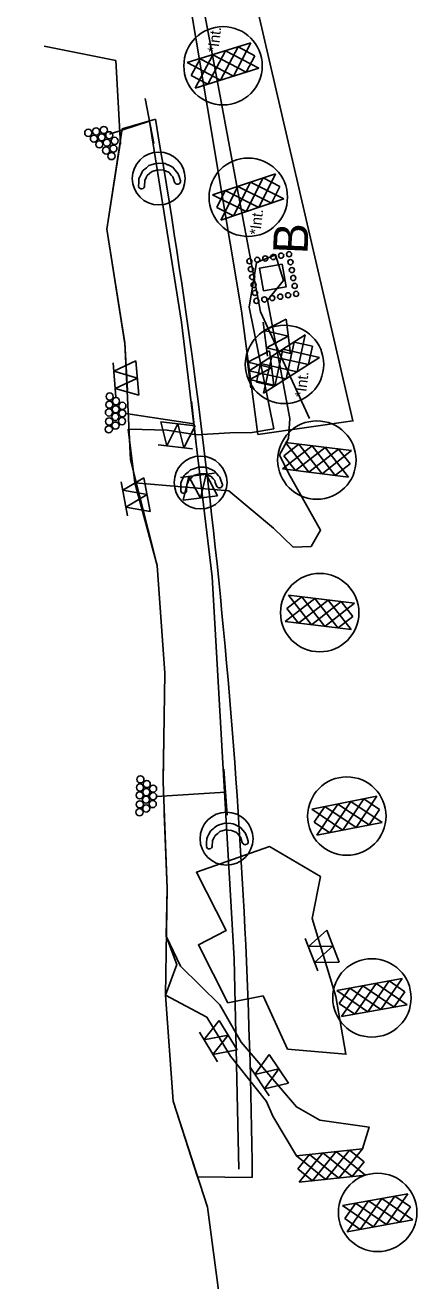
# Model space of a CAD drawing. Extents: x 400935 to 481562, y 415700 to 505362.
# Drawn here: x 481232 to 481402, y 491347 to 491893 of the extents above; entities that cross this region are included whole.
import ezdxf

# ---------------------------------------------------------------- set-up
doc = ezdxf.new("R2010")
doc.units = 0
for name, color, linetype in [('Coir Fiber Wattle with PAM Final CELL', 7, 'Continuous'), ('Drain Terminator Final CELL', 7, 'Continuous'), ('Earth Berm for Slope Drains Final', 7, 'Continuous'), ('Label B Final CELL', 7, 'Continuous'), ('Matting on Slope Note Final CELL', 7, 'Continuous'), ('Old_Level_2', 7, 'Continuous'), ('Rock Inlet Sediment Trap Type B Final CELL', 7, 'Continuous'), ('Rock Silt Check Type A CG CELL', 7, 'Continuous'), ('Rock Silt Check Type A with Matting and PAM Final CELL', 7, 'Continuous'), ('Scratch_Level_3', 7, 'Continuous'), ('Scratch_Level_4', 7, 'Continuous'), ('Slope Drain Final', 7, 'Continuous'), ('Slope Drain Inlet Final CELL', 7, 'Continuous'), ('Special Sediment Control Fence Section Both CELL', 7, 'Continuous'), ('Special Sediment Control Fence Section CG CELL', 7, 'Continuous'), ('Temporary Silt Fence Both', 7, 'Continuous'), ('Temporary Silt Fence CG', 7, 'Continuous'), ('Temporary Silt Fence Final', 7, 'Continuous')]:
    doc.layers.add(name, color=color, linetype=linetype)

msp = doc.modelspace()

# ---------------------------------------------------------------- linework, layer by layer
at = {"layer": 'Coir Fiber Wattle with PAM Final CELL'}
for p, q in [((481289.38, 491830.27), (481286.95, 491829.54)), ((481289.38, 491830.27), (481289.39, 491830.28)), ((481292.02, 491830.14), (481289.39, 491830.28)), ((481283.79, 491825.27), (481283.67, 491823.42)), ((481283.79, 491825.27), (481283.81, 491825.61)), ((481284.45, 491826.94), (481283.81, 491825.61)), ((481284.89, 491827.87), (481284.45, 491826.94)), ((481286.01, 491828.78), (481284.89, 491827.87)), ((481286.95, 491829.54), (481286.01, 491828.78)), ((481292.02, 491830.14), (481293.1, 491829.65)), ((481294.11, 491829.18), (481293.1, 491829.65)), ((481294.11, 491829.18), (481294.33, 491829.09)), ((481295.27, 491827.99), (481294.33, 491829.09)), ((481295.99, 491827.15), (481295.27, 491827.99)), ((481296.23, 491826.39), (481295.99, 491827.15)), ((481296.69, 491824.91), (481296.23, 491826.39)), ((481302.65, 491694.66), (481302.04, 491693.31)), ((481303.07, 491695.6), (481302.65, 491694.66)), ((481304.17, 491696.54), (481303.07, 491695.6)), ((481305.09, 491697.32), (481304.17, 491696.54)), ((481307.5, 491698.12), (481305.09, 491697.32)), ((481307.5, 491698.12), (481307.51, 491698.12)), ((481310.14, 491698.05), (481307.51, 491698.12)), ((481310.14, 491698.05), (481311.23, 491697.58)), ((481312.26, 491697.14), (481311.23, 491697.58)), ((481312.26, 491697.14), (481312.47, 491697.05)), ((481313.44, 491695.97), (481312.47, 491697.05)), ((481314.18, 491695.15), (481313.44, 491695.97)), ((481314.44, 491694.4), (481314.18, 491695.15)), ((481314.94, 491692.93), (481314.44, 491694.4)), ((481302.03, 491692.98), (481301.96, 491691.12)), ((481302.03, 491692.98), (481302.04, 491693.31)), ((481314.38, 491540.92), (481313.93, 491540)), ((481315.51, 491541.82), (481314.38, 491540.92)), ((481316.45, 491542.57), (481315.51, 491541.82)), ((481318.89, 491543.29), (481316.45, 491542.57)), ((481318.89, 491543.29), (481318.9, 491543.29)), ((481321.53, 491543.13), (481318.9, 491543.29)), ((481321.53, 491543.13), (481322.61, 491542.63)), ((481323.61, 491542.15), (481322.61, 491542.63)), ((481323.61, 491542.15), (481323.82, 491542.05)), ((481324.76, 491540.94), (481323.82, 491542.05)), ((481325.47, 491540.1), (481324.76, 491540.94)), ((481313.25, 491538.34), (481313.12, 491536.48)), ((481313.25, 491538.34), (481313.28, 491538.67)), ((481313.93, 491540), (481313.28, 491538.67)), ((481325.7, 491539.34), (481325.47, 491540.1)), ((481326.15, 491537.86), (481325.7, 491539.34))]:
    msp.add_line(p, q, dxfattribs=at)
for points in [[(481281.1, 491823.09), (481281.17, 491824.65), (481281.26, 491826.46), (481281.61, 491827.22), (481282.05, 491828.13), (481282.82, 491829.75), (481282.85, 491829.78), (481283.18, 491830.07), (481283.24, 491830.12), (481283.97, 491830.73), (481284.48, 491831.17), (481285.59, 491832.11), (481286.58, 491832.44), (481289.01, 491833.22), (481289.02, 491833.22), (481291.65, 491833.06), (481292.68, 491832.99), (481293.69, 491832.49), (481293.91, 491832.39), (481294.77, 491831.96), (481295.42, 491831.64), (481295.58, 491831.56), (481295.91, 491831.4), (481295.91, 491831.39), (481296.88, 491830.24), (481297.75, 491829.21), (481298.27, 491828.59), (481298.82, 491826.92), (481299.3, 491825.45)], [(481299.39, 491690.73), (481299.43, 491692.29), (481299.47, 491694.11), (481299.81, 491694.87), (481300.22, 491695.8), (481300.95, 491697.44), (481300.98, 491697.46), (481301.31, 491697.76), (481301.36, 491697.81), (481302.08, 491698.45), (481302.57, 491698.89), (481303.67, 491699.86), (481304.65, 491700.21), (481307.06, 491701.05), (481307.07, 491701.06), (481309.7, 491700.95), (481310.73, 491700.91), (481311.76, 491700.44), (481311.97, 491700.34), (481312.84, 491699.93), (481313.51, 491699.62), (481313.66, 491699.55), (481313.99, 491699.4), (481314, 491699.39), (481315, 491698.26), (481315.89, 491697.25), (481316.42, 491696.64), (481317.01, 491694.99), (481317.53, 491693.53)], [(481310.54, 491536.18), (481310.63, 491537.73), (481310.73, 491539.55), (481311.1, 491540.3), (481311.54, 491541.21), (481312.32, 491542.82), (481312.35, 491542.85), (481312.69, 491543.13), (481312.75, 491543.18), (481313.48, 491543.8), (481313.99, 491544.22), (481315.12, 491545.16), (481316.11, 491545.47), (481318.54, 491546.24), (481318.56, 491546.24), (481321.19, 491546.05), (481322.21, 491545.98), (481323.22, 491545.47), (481323.44, 491545.36), (481324.29, 491544.92), (481324.94, 491544.6), (481325.1, 491544.52), (481325.43, 491544.35), (481325.43, 491544.35), (481326.39, 491543.18), (481327.25, 491542.14), (481327.76, 491541.52), (481328.29, 491539.85), (481328.76, 491538.37)]]:
    msp.add_lwpolyline(points, dxfattribs=at)
for centre in [(481289.85, 491826.5), (481308.05, 491694.36), (481319.32, 491539.51)]:
    msp.add_circle(centre, 11.5, dxfattribs=at)
for centre, radius, start, end in [((481297.98, 491825.28), 1.33, 196.1041, 7.2167), ((481282.39, 491823.25), 1.3, 187.2167, 7.2167), ((481300.67, 491690.93), 1.3, 188.5949, 8.5949), ((481316.21, 491693.33), 1.33, 197.4823, 8.5949), ((481311.83, 491536.33), 1.3, 186.6946, 6.6946), ((481327.44, 491538.21), 1.33, 195.5819, 6.6946)]:
    msp.add_arc(centre, radius, start, end, dxfattribs=at)
at = {"layer": 'Drain Terminator Final CELL'}
for centre in [(481259.24, 491846.34), (481262.62, 491846.95), (481265.99, 491847.55), (481268.35, 491845.3), (481261.69, 491843.79), (481264.05, 491841.34), (481265.07, 491844.4), (481267.33, 491842.05), (481270.71, 491842.85), (481266.97, 491838.69), (481269.33, 491836.25), (481270.16, 491839.5), (481268.54, 491731.72), (481268.38, 491728.19), (481271.14, 491726.16), (481271.3, 491729.69), (481274.06, 491727.66), (481268.22, 491724.8), (481268.31, 491720.85), (481270.99, 491722.9), (481273.9, 491721), (481274.05, 491724.4), (481268.16, 491717.46), (481271.09, 491719.09), (481281.72, 491561.75), (481281.88, 491565.28), (481284.64, 491563.25), (481287.4, 491561.22), (481281.56, 491558.36), (481284.33, 491556.46), (481284.48, 491559.72), (481287.39, 491557.96), (481281.5, 491551.02), (481281.65, 491554.41), (481284.43, 491552.65), (481287.24, 491554.56)]:
    msp.add_circle(centre, 1.55, dxfattribs=at)
at = {"layer": 'Earth Berm for Slope Drains Final'}
msp.add_lwpolyline([(481324.6, 491395.83), (481322.67, 491487.21), (481317.74, 491572.32), (481313.05, 491653.33), (481299.73, 491764.1), (481285.85, 491851.48)], dxfattribs=at)
at = {"layer": 'Matting on Slope Note Final CELL'}
for p, q in [((481288.4, 491852.22), (481274.02, 491848.1)), ((481274.02, 491848.1), (481267.26, 491804.49)), ((481267.26, 491804.49), (481275.12, 491755)), ((481275.12, 491755), (481277.63, 491704.26)), ((481277.63, 491704.26), (481289.1, 491658.31)), ((481289.1, 491658.31), (481292.54, 491611.44)), ((481292.54, 491611.44), (481291.71, 491564.28)), ((481291.71, 491564.28), (481293.47, 491517.85)), ((481293.47, 491517.85), (481292.73, 491471.45)), ((481292.73, 491471.45), (481296.13, 491425.44)), ((481296.13, 491425.44), (481306.74, 491392.57)), ((481306.74, 491392.57), (481330.52, 491392.2))]:
    msp.add_line(p, q, dxfattribs=at)
msp.add_arc((478448.7, 491360.28), 2882, 0.63449, 9.82818, dxfattribs=at)
at = {"layer": 'Old_Level_2'}
for p, q in [((481329.88, 491885.43), (481302.28, 491876.85)), ((481322.28, 491870.97), (481329.88, 491885.43)), ((481305.71, 491865.82), (481313.31, 491880.28)), ((481311.25, 491867.53), (481318.85, 491882)), ((481313.31, 491880.28), (481327.82, 491872.69)), ((481316.74, 491869.25), (481324.39, 491883.72)), ((481318.85, 491882), (481333.31, 491874.4)), ((481324.39, 491883.72), (481331.61, 491879.89)), ((481327.85, 491872.76), (481331.61, 491879.89)), ((481302.28, 491876.85), (481316.74, 491869.25)), ((481303.99, 491871.31), (481307.82, 491878.57)), ((481333.31, 491874.4), (481305.71, 491865.82)), ((481307.82, 491878.57), (481322.28, 491870.97)), ((481303.99, 491871.31), (481311.25, 491867.53)), ((481340.62, 491828.55), (481313.21, 491819.37)), ((481322.38, 491810.25), (481329.66, 491824.88)), ((481327.83, 491812.09), (481335.16, 491826.72)), ((481329.66, 491824.88), (481344.28, 491817.6)), ((481333.33, 491813.93), (481340.62, 491828.55)), ((481335.16, 491826.72), (481342.47, 491823.05)), ((481313.21, 491819.37), (481327.83, 491812.09)), ((481315.04, 491813.86), (481318.71, 491821.21)), ((481316.88, 491808.42), (481324.16, 491823.04)), ((481318.71, 491821.21), (481333.33, 491813.93)), ((481324.16, 491823.04), (481338.83, 491815.77)), ((481338.86, 491815.83), (481342.47, 491823.05)), ((481315.04, 491813.86), (481322.38, 491810.25)), ((481344.28, 491817.6), (481316.88, 491808.42)), ((481353.54, 491758.48), (481329.21, 491742.87)), ((481345.17, 491739.39), (481348.7, 491755.37)), ((481348.7, 491755.37), (481356.68, 491753.6)), ((481350.05, 491742.52), (481353.54, 491758.48)), ((481335.44, 491733.15), (481338.93, 491749.11)), ((481359.77, 491748.75), (481335.44, 491733.15)), ((481338.93, 491749.11), (481354.93, 491745.65)), ((481340.33, 491736.27), (481343.81, 491752.24)), ((481343.81, 491752.24), (481359.77, 491748.75)), ((481354.95, 491745.72), (481356.68, 491753.6)), ((481329.21, 491742.87), (481345.17, 491739.39)), ((481332.33, 491737.98), (481334.09, 491746)), ((481334.09, 491746), (481350.05, 491742.52)), ((481332.33, 491737.98), (481340.33, 491736.27))]:
    msp.add_line(p, q, dxfattribs=at)
for centre in [(481317.79, 491875.49), (481328.75, 491818.35), (481344.52, 491745.68)]:
    msp.add_circle(centre, 17.04, dxfattribs=at)
at = {"layer": 'Rock Inlet Sediment Trap Type B Final CELL'}
msp.add_lwpolyline([(481335.34, 491777.65), (481333.6, 491787.5), (481343.45, 491789.23), (481345.18, 491779.38)], close=True, dxfattribs=at)
for centre in [(481332.69, 491791.14), (481336.14, 491791.75), (481339.59, 491792.36), (481343.04, 491792.96), (481346.48, 491793.57), (481329.25, 491790.53), (481329.86, 491787.08), (481347.09, 491790.13), (481347.7, 491786.68), (481330.46, 491783.64), (481331.07, 491780.19), (481348.31, 491783.23), (481331.68, 491776.74), (481339.18, 491774.51), (481342.63, 491775.12), (481346.08, 491775.73), (481348.92, 491779.79), (481349.52, 491776.34), (481332.29, 491773.3), (481335.74, 491773.91)]:
    msp.add_circle(centre, 1.12, dxfattribs=at)
at = {"layer": 'Rock Silt Check Type A CG CELL'}
for p, q in [((481349.71, 491401.65), (481378.44, 491404.7)), ((481378.44, 491404.7), (481368.18, 491391.99)), ((481362.41, 491391.38), (481349.71, 491401.65)), ((481355.38, 491402.2), (481350.3, 491395.93)), ((481361.19, 491402.87), (481350.92, 491390.16)), ((481368.18, 491391.99), (481355.42, 491402.26)), ((481366.96, 491403.48), (481356.64, 491390.77)), ((481373.9, 491392.6), (481361.19, 491402.87)), ((481372.68, 491404.1), (481362.41, 491391.38)), ((481379.66, 491393.21), (481366.96, 491403.48)), ((481379.06, 491398.98), (481372.68, 491404.1)), ((481379.06, 491398.98), (481373.9, 491392.6)), ((481356.64, 491390.77), (481350.3, 491395.93)), ((481350.92, 491390.16), (481379.66, 491393.21))]:
    msp.add_line(p, q, dxfattribs=at)
at = {"layer": 'Rock Silt Check Type A with Matting and PAM Final CELL'}
for p, q in [((481343.58, 491700.23), (481356.45, 491710.29)), ((481344.27, 491705.94), (481350.74, 491710.99)), ((481344.98, 491711.69), (481355.05, 491698.83)), ((481373.67, 491708.19), (481344.98, 491711.69)), ((481350.74, 491710.99), (481360.81, 491698.13)), ((481356.45, 491710.29), (481366.56, 491697.42)), ((481344.27, 491705.94), (481349.34, 491699.51)), ((481349.34, 491699.51), (481362.21, 491709.59)), ((481355.05, 491698.83), (481367.96, 491708.89)), ((481360.81, 491698.13), (481373.67, 491708.19)), ((481362.21, 491709.59), (481372.27, 491696.73)), ((481367.96, 491708.89), (481372.98, 491702.43)), ((481372.27, 491696.73), (481343.58, 491700.23)), ((481366.62, 491697.47), (481372.98, 491702.43)), ((481345.49, 491639.61), (481351.97, 491644.66)), ((481346.21, 491645.36), (481356.27, 491632.5)), ((481374.89, 491641.86), (481346.21, 491645.36)), ((481351.97, 491644.66), (481362.03, 491631.8)), ((481344.81, 491633.9), (481357.67, 491643.96)), ((481345.49, 491639.61), (481350.56, 491633.18)), ((481350.56, 491633.18), (481363.43, 491643.26)), ((481356.27, 491632.5), (481369.19, 491642.56)), ((481357.67, 491643.96), (481367.79, 491631.09)), ((481362.03, 491631.8), (481374.89, 491641.86)), ((481363.43, 491643.26), (481373.49, 491630.4)), ((481369.19, 491642.56), (481374.2, 491636.1)), ((481373.49, 491630.4), (481344.81, 491633.9)), ((481367.84, 491631.14), (481374.2, 491636.1)), ((481384.67, 491557.93), (481356.31, 491552.34)), ((481375.57, 491544.36), (481384.67, 491557.93)), ((481356.31, 491552.34), (481369.88, 491543.24)), ((481357.42, 491546.65), (481362, 491553.46)), ((481358.55, 491541.01), (481367.65, 491554.57)), ((481362, 491553.46), (481375.57, 491544.36)), ((481364.24, 491542.12), (481373.34, 491555.69)), ((481367.65, 491554.57), (481381.26, 491545.48)), ((481369.88, 491543.24), (481379.03, 491556.81)), ((481373.34, 491555.69), (481386.9, 491546.59)), ((481379.03, 491556.81), (481385.8, 491552.24)), ((481381.3, 491545.54), (481385.8, 491552.24)), ((481357.42, 491546.65), (481364.24, 491542.12)), ((481386.9, 491546.59), (481358.55, 491541.01)), ((481395.68, 491478.7), (481367.25, 491473.51)), ((481369.32, 491462.14), (481378.61, 491475.58)), ((481375.03, 491463.17), (481384.32, 491476.62)), ((481378.61, 491475.58), (481392.1, 491466.3)), ((481380.69, 491464.22), (481390.02, 491477.66)), ((481384.32, 491476.62), (481397.75, 491467.34)), ((481386.39, 491465.26), (481395.68, 491478.7)), ((481390.02, 491477.66), (481396.73, 491472.99)), ((481367.25, 491473.51), (481380.69, 491464.22)), ((481368.28, 491467.8), (481372.95, 491474.55)), ((481372.95, 491474.55), (481386.39, 491465.26)), ((481392.14, 491466.36), (481396.73, 491472.99)), ((481368.28, 491467.8), (481375.03, 491463.17)), ((481397.75, 491467.34), (481369.32, 491462.14)), ((481369.71, 491380.02), (481398.15, 491385.16)), ((481386.78, 491383.11), (481377.42, 491369.68)), ((481392.44, 491384.14), (481383.13, 491370.71)), ((481400.2, 491373.8), (481386.78, 491383.11)), ((481398.15, 491385.16), (481388.84, 491371.74)), ((481399.18, 491379.51), (481392.44, 491384.14)), ((481383.13, 491370.71), (481369.71, 491380.02)), ((481375.33, 491380.98), (481370.72, 491374.36)), ((481381.07, 491382.07), (481371.77, 491368.65)), ((481388.84, 491371.74), (481375.37, 491381.04)), ((481394.5, 491372.76), (481381.07, 491382.07)), ((481399.18, 491379.51), (481394.5, 491372.76)), ((481377.42, 491369.68), (481370.72, 491374.36)), ((481371.77, 491368.65), (481400.2, 491373.8))]:
    msp.add_line(p, q, dxfattribs=at)
for centre in [(481358.57, 491704.09), (481359.79, 491637.76), (481371.59, 491549.33), (481382.48, 491470.29), (481384.98, 491377.04)]:
    msp.add_circle(centre, 17.04, dxfattribs=at)
at = {"layer": 'Scratch_Level_3'}
msp.add_lwpolyline([(481355.37, 491722.18), (481334.07, 491768.58), (481324.82, 491817.76), (481315.61, 491866.95), (481306.43, 491916.15), (481298.76, 491965.69), (481287.96, 492014.51), (481278.67, 492063.68), (481265.49, 492111.96), (481256.21, 492161.13), (481244.98, 492209.85), (481231.8, 492258.12)], dxfattribs=at)
at = {"layer": 'Scratch_Level_4'}
msp.add_lwpolyline([(481332.89, 491715.21), (481374.23, 491721.13), (481289.04, 492088.86), (481252.67, 492080.43), (481273.82, 491989.14), (481294.57, 491948.38), (481300.91, 491917.87), (481325.82, 491768.95)], close=True, dxfattribs=at)
at = {"layer": 'Slope Drain Final'}
for p, q in [((481285.85, 491851.48), (481268.52, 491845.77)), ((481305.13, 491719.82), (481275.6, 491724.32)), ((481318.85, 491559.72), (481288.94, 491557.88))]:
    msp.add_line(p, q, dxfattribs=at)
at = {"layer": 'Slope Drain Inlet Final CELL'}
for p, q in [((481287.72, 491841.65), (481283.99, 491861.3)), ((481306.23, 491709.88), (481304.03, 491729.76)), ((481319.56, 491549.75), (481318.14, 491569.7))]:
    msp.add_line(p, q, dxfattribs=at)
at = {"layer": 'Special Sediment Control Fence Section Both CELL'}
for p, q in [((481271.2, 491731.46), (481270, 491746.41)), ((481281.17, 491732.25), (481279.97, 491747.2)), ((481276.28, 491679.88), (481273.59, 491694.64)), ((481286.12, 491681.68), (481283.43, 491696.43))]:
    msp.add_line(p, q, dxfattribs=at)
for points in [[(481280.57, 491739.73), (481270.3, 491742.67), (481279.97, 491747.2)], [(481281.17, 491732.25), (481270.9, 491735.19), (481280.57, 491739.73)], [(481284.78, 491689.06), (481274.26, 491690.95), (481283.43, 491696.43)], [(481286.12, 491681.68), (481275.61, 491683.57), (481284.78, 491689.06)]]:
    msp.add_lwpolyline(points, dxfattribs=at)
at = {"layer": 'Special Sediment Control Fence Section CG CELL'}
for p, q in [((481347.06, 491750.46), (481345.16, 491765.34)), ((481337.14, 491749.19), (481335.24, 491764.07)), ((481329.94, 491735.44), (481328.03, 491750.32)), ((481339.85, 491736.71), (481337.95, 491751.59)), ((481305.66, 491718.96), (481290.77, 491720.7)), ((481304.5, 491709.03), (481289.6, 491710.77)), ((481299.25, 491696.55), (481314.13, 491698.45)), ((481300.52, 491686.63), (481315.4, 491688.53)), ((481368.28, 491485.76), (481362.83, 491499.74)), ((481358.96, 491482.13), (481353.51, 491496.11)), ((481323.88, 491447.66), (481316.13, 491460.5)), ((481315.32, 491442.49), (481307.57, 491455.33)), ((481346.21, 491433.22), (481337.91, 491445.72)), ((481337.88, 491427.69), (481329.58, 491440.18))]:
    msp.add_line(p, q, dxfattribs=at)
for points in [[(481346.11, 491757.9), (481335.72, 491760.35), (481345.16, 491765.34)], [(481347.06, 491750.46), (481336.67, 491752.91), (481346.11, 491757.9)], [(481338.9, 491744.15), (481328.51, 491746.6), (481337.95, 491751.59)], [(481339.85, 491736.71), (481329.46, 491739.16), (481338.9, 491744.15)], [(481298.21, 491719.83), (481293.33, 491710.34), (481290.77, 491720.7)], [(481305.66, 491718.96), (481300.77, 491709.46), (481298.21, 491719.83)], [(481300.52, 491686.63), (481302.97, 491697.02), (481307.96, 491687.58)], [(481307.96, 491687.58), (481310.41, 491697.98), (481315.4, 491688.53)], [(481365.55, 491492.75), (481354.87, 491492.62), (481362.83, 491499.74)], [(481368.28, 491485.76), (481357.6, 491485.63), (481365.55, 491492.75)], [(481320, 491454.08), (481309.51, 491452.12), (481316.13, 491460.5)], [(481323.88, 491447.66), (481313.38, 491445.7), (481320, 491454.08)], [(481342.06, 491439.47), (481331.66, 491437.06), (481337.91, 491445.72)], [(481346.21, 491433.22), (481335.81, 491430.81), (481342.06, 491439.47)]]:
    msp.add_lwpolyline(points, dxfattribs=at)
at = {"layer": 'Temporary Silt Fence Both'}
for p, q in [((481276.27, 491734.27), (481275.12, 491755)), ((481291.73, 491565.54), (481292.04, 491583.11)), ((481293.47, 491517.85), (481292.23, 491550.52)), ((481293.12, 491497.2), (481293.47, 491517.85))]:
    msp.add_line(p, q, dxfattribs=at)
for points in [[(481273.24, 491841.38), (481271.15, 491877.73), (481240.04, 491883.96)], [(481275.18, 491754.63), (481267.26, 491804.49), (481273.03, 491841.72)], [(481292.04, 491583.11), (481292.54, 491611.44), (481289.1, 491658.31), (481279.43, 491694.22)]]:
    msp.add_lwpolyline(points, dxfattribs=at)
at = {"layer": 'Temporary Silt Fence CG'}
for points in [[(481356.07, 491666.49), (481360.18, 491673.63), (481346.2, 491698.46), (481342.27, 491706.37), (481346.21, 491713.43), (481346.85, 491722.2), (481337.14, 491773.64), (481344.11, 491782.17), (481340.64, 491793.37), (481332.29, 491789.91), (481329.12, 491770.53), (481339.84, 491717.74), (481330.42, 491716.08), (481320.79, 491715.98), (481306.27, 491715.05), (481293.55, 491717.08), (481277.19, 491717.54)], [(481279.43, 491694.22), (481320.33, 491690.71), (481339.73, 491674.46), (481348.32, 491666.19), (481356.07, 491666.49)], [(481378.44, 491404.7), (481381.26, 491414.1), (481359.89, 491417.09), (481349.69, 491422.91), (481325.61, 491451.06), (481316.38, 491467.24), (481299.34, 491484.03), (481293.12, 491497.2)], [(481292.73, 491471.45), (481310.82, 491461.88), (481321, 491444.93), (481336.7, 491425.2), (481339.46, 491418.81), (481349.71, 491401.65), (481349.71, 491401.65)]]:
    msp.add_lwpolyline(points, dxfattribs=at)
msp.add_lwpolyline([(481319.93, 491468.22), (481307.1, 491493.43), (481319.14, 491499.56), (481306.24, 491524.92), (481337.92, 491536.05), (481360.09, 491523.03), (481356.58, 491504.85), (481366.86, 491470.86), (481371.17, 491445.79), (481345.83, 491448.07), (481335.23, 491471.19)], close=True, dxfattribs=at)
at = {"layer": 'Temporary Silt Fence Final'}
msp.add_line((481279.43, 491694.22), (481276.53, 491717.58), dxfattribs=at)
for points in [[(481293.12, 491497.2), (481297.7, 491484.8), (481292.73, 491471.45)], [(481314.3, 491265.21), (481323.56, 491285.13), (481311.02, 491379.31), (481296.13, 491425.44), (481292.73, 491471.45), (481292.73, 491471.45)]]:
    msp.add_lwpolyline(points, dxfattribs=at)

# ---------------------------------------------------------------- texts
at = {"layer": 'Label B Final CELL'}
msp.add_text('B', height=15, rotation=87.5918, dxfattribs=at).set_placement((481354.48, 491793.46))
at = {"layer": 'Old_Level_2'}
for p in [(481315.69, 491881.02), (481333.93, 491801.78), (481353.65, 491731.14)]:
    msp.add_text('*Int.', height=4.746, rotation=83.0423, dxfattribs=at).set_placement(p)

doc.saveas('drawing.dxf')
